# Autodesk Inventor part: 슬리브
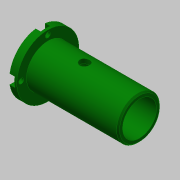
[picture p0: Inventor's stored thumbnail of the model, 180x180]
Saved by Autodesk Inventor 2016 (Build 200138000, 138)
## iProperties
Created: 2019-10
Part Number: 슬리브
Material: 알루미늄 6061
Document SubType Name: Modeling
Designer: mduedu
Density: 1 g/cm^3
Appearance: 진녹색
Author: mduedu
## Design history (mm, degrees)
sketch "스케치1"
  geometry: L1 (0, 0)-(5, 0); L2 (5, 0)-(5, 21); L3 (5, 21)-(0, 21); L4 (0, 21)-(0, 0); L5 (5, 0)-(67, 0); L6 (67, 0)-(67, 14.5); L7 (67, 14.5)-(5, 14.5); L8 (5, 14.5)-(5, 0)
  constraints: 16 end point, 4 parallel, 2 horizontal, 2 perpendicular
  dimensions: "d0" = 67 distance between parallel lines of L6 L4; "d2" = 62 distance of L6.end L7.end; "d3" = 42 diameter of L3 L1; "d4" = 29 diameter of L7 L5
revolve "회전1" sketch "스케치1" stored, may be unused: angle "d5" = 90 deg
hole "구멍1" diameter "d8" = 23; stored, may be unused: countersink angle "d12" = 90 deg, drill point angle "d14" = 118 deg; dims "d6" = 10, "d7" = 10, "d9" = 6, "d10" = 4, "d11" = 2, "d13" = 8
sketch "스케치2"
  geometry: L1 (-5, 21)-(-5, -21) reference; C1 r 3.3 at (-30, 0); 1 further point
  constraints: 1 centre point, 1 horizontal alignment
  dimensions: "d15" = 6.6 diameter of C1; "d16" = 25 distance from line of C1.centre L1
extrude "돌출1" cut sketch "스케치2" stored distance "d17" = 10; taper "d18" = 0 deg
chamfer "모따기1" distance "d19" = 1; stored, may be unused: second distance "d20" = 2, angle "d21" = 45 deg
sketch "스케치3" dims "d22" = 36
  geometry: 6 further points
  constraints: 2 vertical alignment, 1 coincident, 7 other
  dimensions: "d25" = 360 deg dimension on point (0, 0) point (0, 18) (derived)
sketch "스케치4"
  geometry: 4 further points
  constraints: 4 other
hole "구멍2" sketch "스케치4" at (-18, 0), (0, -18), (18, 0), (0, 18) diameter "d27" = 3.4; stored, may be unused: countersink angle "d31" = 90 deg, drill point angle "d33" = 0 deg; dims "d28" = 6, "d29" = 6.5, "d30" = 3.4, "d32" = 8
sketch "스케치5"
  geometry: L1 (-21.25, 20.747)-(-21.25, 18); L2 (-14.75, 18)-(-14.75, 20.747); A1 r 3.25 centre (-18, 18) between (-19.349, 20.957) and (-16.651, 20.957) reference; A2 r 21 centre (-18, 0) between (-19.349, 20.957) and (-38.957, 1.349) reference; A3 r 21 centre (-18, 0) between (2.957, 1.349) and (-16.651, 20.957) reference; A4 r 21 centre (-18, 0) between (-14.75, 20.747) and (-21.25, 20.747); A5 r 3.25 centre (-18, 18) between (-21.25, 18) and (-14.75, 18); 1 further point
  constraints: 8 point on circle, 4 end point, 2 centre point, 2 coincident, 2 tangent, 1 parallel, 1 vertical
extrude "돌출2" cut sketch "스케치5" stored distance "d34" = 10; taper "d35" = 0 deg
node "솔리드1"
pattern_circular "원형 패턴1" dims angle "d37" = 360 deg
